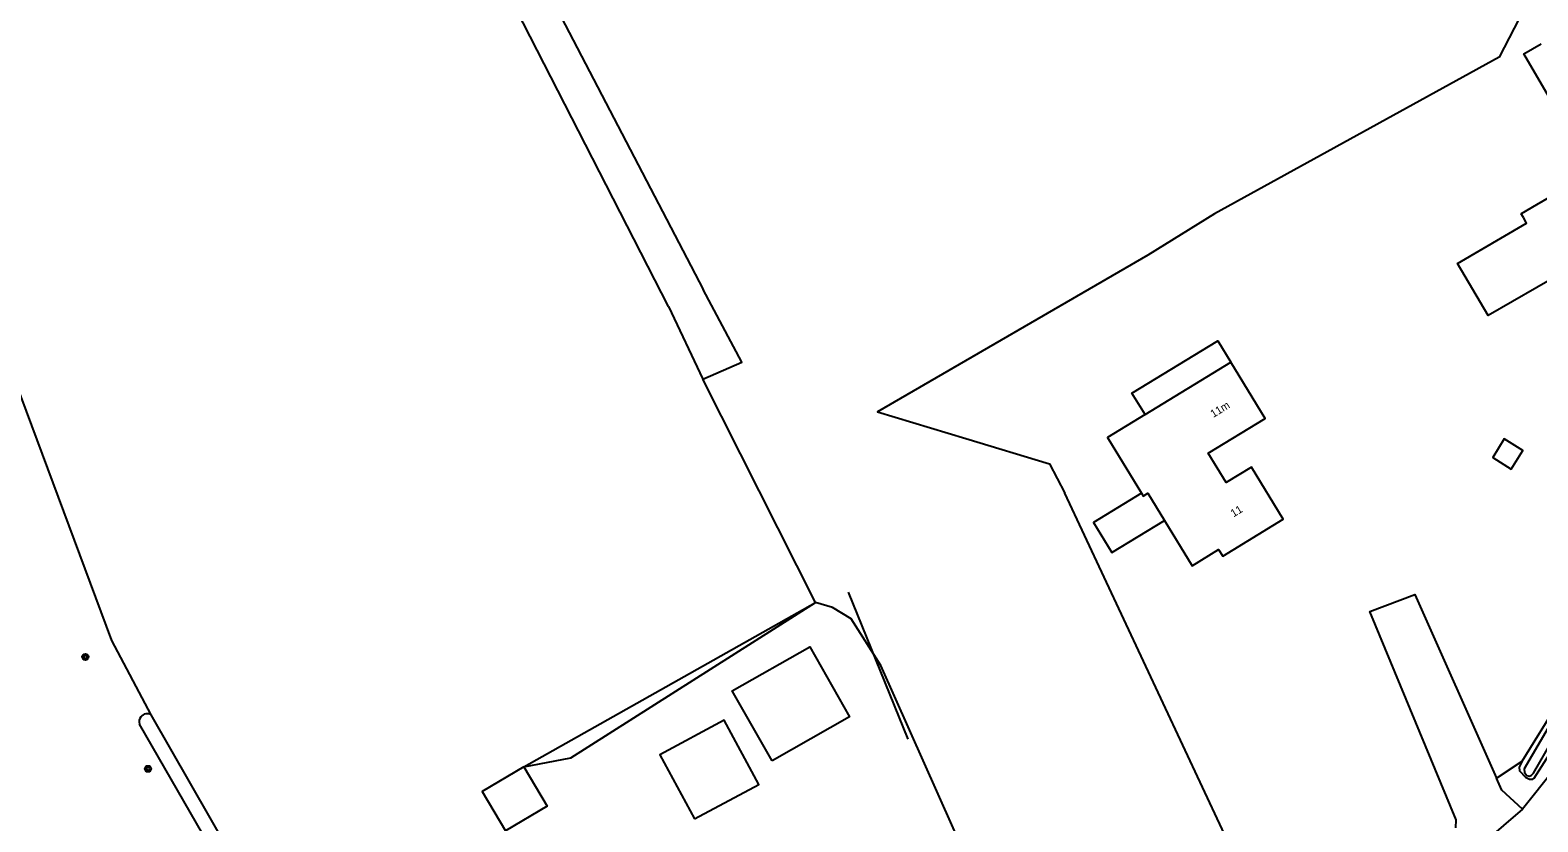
# Model space of a CAD drawing. Extents: x 141000 to 143000, y 400580 to 403500.
# Drawn here: x 141417.1 to 141610, y 402813.4 to 402914.6 of the extents above; entities that cross this region are included whole.
import ezdxf

# ---------------------------------------------------------------- set-up
doc = ezdxf.new("R2010")
doc.units = 0
for name, color, linetype in [('gg-afsc-erfafscheiding', 7, 'Continuous'), ('gg-afsc-hekwerk', 7, 'Continuous'), ('gg-anno-huisnummerreeks BGT', 7, 'Continuous'), ('gg-bbg-bijgebouw', 7, 'Continuous'), ('gg-bbg-hoofdgebouw', 7, 'Continuous'), ('gg-bbg-luifel en loopbrug', 7, 'Continuous'), ('gg-bbg-overig bouwwerk', 7, 'Continuous'), ('gg-knt-bronhoudergrens', 7, 'Continuous'), ('gg-knt-verharding', 7, 'Continuous'), ('gg-knt-verharding nz', 7, 'Continuous'), ('gg-kntw-bovenkant insteek waterloop', 7, 'Continuous'), ('gg-kntw-waterlijn', 7, 'Continuous'), ('gt-symb-boom', 7, 'Continuous')]:
    doc.layers.add(name, color=color, linetype=linetype)

# ---------------------------------------------------------------- blocks, each defined once
blk = doc.blocks.new('gt0-BOOM')
at = {"layer": 'gt-symb-boom'}
for radius in [0.4, 0.2]:
    blk.add_circle((0, 0), radius, dxfattribs=at)

msp = doc.modelspace()

# ---------------------------------------------------------------- linework, layer by layer
at = {"layer": 'gg-afsc-erfafscheiding'}
msp.add_line((141604.73, 402818.98), (141608.01, 402821.12), dxfattribs=at)
at = {"layer": 'gg-afsc-hekwerk'}
for p, q in [((141517.62, 402841.44), (141503.18, 402869.98)), ((141521.8, 402842.74), (141529.41, 402823.94))]:
    msp.add_line(p, q, dxfattribs=at)
msp.add_lwpolyline([(141480.3, 402820.42), (141486.3, 402821.55), (141517.62, 402841.44)], dxfattribs=at)
at = {"layer": 'gg-bbg-bijgebouw'}
for points in [[(141512.05, 402821.17), (141506.97, 402830.13), (141516.89, 402835.77), (141521.98, 402826.8), (141512.05, 402821.17)], [(141502.11, 402813.74), (141510.35, 402818.17), (141505.93, 402826.37), (141497.7, 402821.93), (141502.11, 402813.74)], [(141480.3, 402820.42), (141474.96, 402817.27), (141477.94, 402812.22)], [(141480.3, 402820.42), (141483.28, 402815.37), (141477.94, 402812.22)]]:
    msp.add_lwpolyline(points, dxfattribs=at)
at = {"layer": 'gg-bbg-hoofdgebouw'}
msp.add_line((141559.77, 402865.48), (141570.74, 402872.16), dxfattribs=at)
for points in [[(141608.18, 402890.65), (141607.89, 402891.15), (141607.95, 402891.18), (141609.91, 402892.32), (141615.34, 402895.48), (141619.35, 402888.58), (141612.45, 402884.56), (141613.03, 402883.52), (141603.67, 402878.14), (141599.76, 402884.8), (141608.58, 402889.96), (141608.18, 402890.65)], [(141562.25, 402851.92), (141565.78, 402846.13), (141569.19, 402848.21), (141569.71, 402847.36), (141577.44, 402852.07), (141573.38, 402858.72), (141570.16, 402856.76), (141567.86, 402860.54), (141575.13, 402864.97), (141570.74, 402872.16)], [(141559.77, 402865.48), (141554.97, 402862.55), (141559.32, 402855.4)], [(141559.32, 402855.4), (141559.55, 402855.04), (141560.13, 402855.39), (141562.25, 402851.92)]]:
    msp.add_lwpolyline(points, dxfattribs=at)
at = {"layer": 'gg-bbg-luifel en loopbrug'}
for points in [[(141611.4, 402906.19), (141608.25, 402911.61), (141610.45, 402912.88)], [(141559.77, 402865.48), (141558.1, 402868.21), (141569.08, 402874.9), (141570.74, 402872.16)], [(141559.32, 402855.4), (141553.17, 402851.66), (141555.52, 402847.82), (141562.25, 402851.92)]]:
    msp.add_lwpolyline(points, dxfattribs=at)
at = {"layer": 'gg-bbg-overig bouwwerk'}
msp.add_lwpolyline([(141606.62, 402858.5), (141608.1, 402860.88), (141605.73, 402862.36), (141604.25, 402859.98), (141606.62, 402858.5)], dxfattribs=at)
at = {"layer": 'gg-knt-bronhoudergrens'}
for p, q in [((141498.79, 402879.27), (141470.33, 402934.89)), ((141480.3, 402820.42), (141517.62, 402841.44))]:
    msp.add_line(p, q, dxfattribs=at)
for points in [[(141602.45, 402935.13), (141607.84, 402921.1), (141608.6, 402918.27), (141607.62, 402916.13), (141605.08, 402911.18), (141568.66, 402891.14), (141560.11, 402885.86), (141525.54, 402865.81), (141536.84, 402862.4), (141547.53, 402859.18), (141549.51, 402855.41)], [(141479.84, 402931.97), (141478.82, 402930.27), (141479.87, 402926.3), (141503.22, 402881.45)], [(141432.62, 402827.07), (141427.58, 402836.55), (141407.77, 402889.73)], [(141498.79, 402879.27), (141503.18, 402869.98), (141508.17, 402872.18), (141503.22, 402881.45)], [(141575.33, 402800.6), (141574.82, 402801.17), (141574.65, 402801.68), (141549.51, 402855.41)], [(141546.04, 402788.33), (141525.98, 402833.36), (141522.17, 402839.33), (141519.79, 402840.79), (141517.62, 402841.44)]]:
    msp.add_lwpolyline(points, dxfattribs=at)
at = {"layer": 'gg-knt-verharding'}
for points in [[(141636.3, 402866.21), (141621.01, 402836.32), (141616.71, 402828.12), (141612.12, 402820.08), (141608.07, 402815.01)], [(141599.53, 402812.62), (141599.59, 402813.64), (141588.52, 402840.27), (141594.29, 402842.43), (141604.73, 402818.98)], [(141608.07, 402815.01), (141605.42, 402817.43), (141604.73, 402818.98)]]:
    msp.add_lwpolyline(points, dxfattribs=at)
at = {"layer": 'gg-knt-verharding nz'}
msp.add_line((141608.07, 402815.01), (141599.24, 402807.46), dxfattribs=at)
at = {"layer": 'gg-kntw-bovenkant insteek waterloop'}
msp.add_line((141458.13, 402779.11), (141431.11, 402825.86), dxfattribs=at)
for points in [[(141608.01, 402821.12), (141612.67, 402828.65), (141616.63, 402836.32), (141623.31, 402849.55), (141631.77, 402865.85), (141632.36, 402866.93)], [(141608.01, 402821.12), (141607.62, 402820.38), (141607.67, 402819.88), (141608.45, 402819.07), (141608.95, 402818.82), (141609.37, 402818.82), (141609.54, 402818.95), (141614.07, 402826.02), (141623.78, 402845.8), (141633.19, 402863.79), (141634.22, 402865.8)], [(141471.8, 402759.95), (141462.62, 402774.68), (141432.62, 402827.07)]]:
    msp.add_lwpolyline(points, dxfattribs=at)
for start, end in [(140.9531, 196.7049), (60.4204, 141.1123)]:
    msp.add_arc((141432.11, 402826.16), 1.04, start, end, dxfattribs=at)
at = {"layer": 'gg-kntw-waterlijn'}
msp.add_lwpolyline([(141632.81, 402866.43), (141623.77, 402849.47), (141618.2, 402838.55), (141614.57, 402831.14), (141612.39, 402827.14), (141608.27, 402820.16), (141608.3, 402819.68), (141608.61, 402819.32), (141608.97, 402819.22), (141609.22, 402819.35), (141609.49, 402819.62), (141613.81, 402827.15), (141615.19, 402829.74), (141618.9, 402837.32), (141622.02, 402843.24), (141624.85, 402848.99), (141627.53, 402854.22), (141631.49, 402861.51), (141633.73, 402865.97)], dxfattribs=at)

# ---------------------------------------------------------------- block references
at = {"layer": 'gt-symb-boom'}
for p in [(141424.21, 402834.47), (141432.22, 402820.15)]:
    msp.add_blockref('gt0-BOOM', p, dxfattribs=at)

# ---------------------------------------------------------------- texts
at = {"layer": 'gg-anno-huisnummerreeks BGT'}
for s, p in [('11m', (141568.51, 402865.03)), ('11', (141571.09, 402852.3))]:
    msp.add_text(s, height=1, rotation=31.4, dxfattribs=at).set_placement(p)

doc.saveas('drawing.dxf')
